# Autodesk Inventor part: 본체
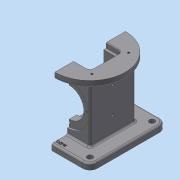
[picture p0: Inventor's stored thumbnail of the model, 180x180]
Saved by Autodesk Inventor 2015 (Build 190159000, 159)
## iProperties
Created: 2021-05
Part Number: 본체
Material: 일반
Document SubType Name: Modeling
Designer: 101258642
Density: 1 g/cm^3
Appearance: 기본값
Author: 101258642
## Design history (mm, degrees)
sketch "스케치6"
  geometry: L1 (37, -37)-(-37, -37); L2 (-37, -37)-(-37, 37); L3 (-37, 37)-(37, 37); L4 (37, 37)-(37, -37); L5 (37, -37)-(-37, 37); L6 (-37, -37)-(37, 37); 1 further point
  constraints: 12 end point, 2 midpoint, 2 parallel, 1 horizontal, 1 perpendicular
  dimensions: "d4" = 74 distance of L2.end L3.end; "d5" = 74 distance of L1.end L2.end
extrude "돌출2" new body sketch "스케치6" stored distance "d6" = 108; taper "d7" = 0 deg
sketch "스케치7"
  geometry: C1 r 57.5 at (0, 0); 1 further point
  constraints: 1 centre point, 1 coincident
  dimensions: "d8" = 57.5 radius of C1
extrude "돌출3" join sketch "스케치7" distance "d9" = 10; taper "d10" = 0 deg
sketch "스케치8"
  geometry: L1 (-62.5, 62.5)-(62.5, 62.5); L2 (62.5, 62.5)-(62.5, -62.5); L3 (62.5, -62.5)-(-62.5, -62.5); L4 (-62.5, -62.5)-(-62.5, 62.5); L5 (-62.5, 62.5)-(62.5, -62.5); L6 (62.5, 62.5)-(-62.5, -62.5); 1 further point
  constraints: 12 end point, 2 midpoint, 2 parallel, 1 horizontal, 1 perpendicular
  dimensions: "d11" = 125 distance of L2.end L3.end; "d12" = 125 distance of L1.end L2.end
extrude "돌출4" join sketch "스케치8" distance "d13" = 10; taper "d14" = 0 deg
sketch "스케치9"
  geometry: L1 (-37, 44)-(-57.5, 44) reference; L2 (-57.5, 44)-(-57.5, 54) reference; L3 (-57.5, 54)-(57.5, 54) reference; L4 (57.5, 54)-(57.5, 44) reference; L5 (57.5, 44)-(37, 44) reference; L6 (37, 44)-(37, -44) reference; L7 (37, -44)-(62.5, -44) reference; L8 (62.5, -44)-(62.5, -54) reference; L9 (62.5, -54)-(-62.5, -54) reference; L10 (-62.5, -54)-(-62.5, -44) reference; L11 (-62.5, -44)-(-37, -44) reference; L12 (-37, -44)-(-37, 44) reference; L13 (-37, 0)-(-34, 0); L14 (-34, 0)-(-34, 35); L15 (-34, 35)-(-37, 35); L16 (-37, 35)-(-37, 0); L17 (37, 44)-(37, -44) reference; L18 (37, 35)-(34, 35); L19 (34, 35)-(34, 0); L20 (34, 0)-(37, 0); L21 (37, 0)-(37, 35); L22 (-34, 0)-(34, 0); L23 (34, 0)-(34, 24); L24 (34, 24)-(-34, 24); L25 (-34, 24)-(-34, 0); 1 further point
  constraints: 24 end point, 6 parallel, 3 horizontal, 3 perpendicular, 3 point on line, 1 midpoint
  dimensions: "d15" = 54 distance between parallel lines of L9 L13; "d16" = 3 distance of L14.end L15.end; "d17" = 3 distance of L18.start L18.end; "d18" = 48 diameter of L24 L22; "d19" = 70 diameter of L15 L22; "d20" = 70 diameter of L18 L20
revolve "회전1" sketch "스케치9" stored, may be unused: angle "d21" = 90 deg
sketch "스케치11"
  geometry: L1 (-26, 26)-(26, 26); L2 (26, 26)-(26, -26); L3 (26, -26)-(-26, -26); L4 (-26, -26)-(-26, 26); L5 (-26, 26)-(26, -26); L6 (26, 26)-(-26, -26); C1 r 57.5 at (0, 0) reference
  constraints: 12 end point, 2 midpoint, 2 parallel, 1 horizontal, 1 perpendicular
  dimensions: "d26" = 52 distance of L2.end L3.end; "d27" = 52 distance of L1.end L2.end
extrude "돌출6" cut sketch "스케치11" distance "d28" = 8; taper "d29" = 0 deg
sketch "스케치12" dims "d30" = 29
  geometry: C1 r 35 at (0, 0) reference; 2 further points
  constraints: 1 coincident, 1 vertical alignment, 2 other
hole "구멍1" sketch "스케치12" at (0, 29) diameter "d31" = 3.242; stored, may be unused: countersink angle "d35" = 90 deg, drill point angle "d37" = 118 deg; dims "d32" = 8, "d33" = 4, "d34" = 2, "d36" = 10
sketch "스케치13"
  geometry: L1 (-30, 33)-(30, 33); L2 (30, 33)-(30, -33); L3 (30, -33)-(-30, -33); L4 (-30, -33)-(-30, 33); L5 (-30, 33)-(30, -33); L6 (30, 33)-(-30, -33); C1 r 57.5 at (0, 0) reference; 4 further points
  constraints: 12 end point, 4 coincident, 2 midpoint, 2 parallel, 1 horizontal, 1 perpendicular
  dimensions: "d41" = 60 distance of L2.end L3.end; "d42" = 66 distance of L1.end L2.end
hole "구멍2" sketch "스케치13" at (-30, -33), (-30, 33), (30, 33), (30, -33) diameter "d43" = 3.242; stored, may be unused: countersink angle "d47" = 90 deg, drill point angle "d49" = 118 deg; dims "d44" = 8, "d45" = 4, "d46" = 2, "d48" = 10
fillet "모깎기1" dims "d50" = 12
hole "구멍3" diameter "d53" = 9; stored, may be unused: countersink angle "d57" = 90 deg, drill point angle "d59" = 0 deg; dims "d51" = 10, "d52" = 10, "d54" = 8, "d55" = 4, "d56" = 2, "d58" = 10
sketch "스케치15"
  geometry: L1 (26, 46)-(26, 54) reference; L2 (26, 54)-(57.5, 54) reference; L3 (57.5, 54)-(57.5, 44) reference; L4 (57.5, 44)-(37, 44) reference; L5 (37, 44)-(37, 35) reference; L6 (37, 35)-(34, 35) reference; L7 (34, 35)-(34, 30.621) reference; L8 (34, 30.621)-(24, 30.621) reference; L9 (24, 30.621)-(23.026, 29) reference; L10 (23.026, 29)-(24, 27.379) reference; L11 (24, 27.379)-(34, 27.379) reference; L12 (34, 27.379)-(34, 24) reference; L13 (34, 24)-(-34, 24) reference; L14 (-26, 46)-(26, 46) reference; L15 (-34, -24)-(34, -24) reference; L16 (34, -24)-(34, -27.379) reference; L17 (34, -27.379)-(24, -27.379) reference; L18 (24, -27.379)-(23.026, -29) reference; L19 (23.026, -29)-(24, -30.621) reference; L20 (24, -30.621)-(34, -30.621) reference; L21 (34, -30.621)-(34, -35) reference; L22 (34, -35)-(37, -35) reference; L23 (37, -35)-(37, -44) reference; L24 (37, -44)-(62.5, -44) reference; L25 (62.5, -44)-(62.5, -54) reference; L26 (62.5, -54)-(-62.5, -54) reference; L27 (-62.5, -54)-(-62.5, -44) reference; L28 (-62.5, -44)-(-37, -44) reference; L29 (-37, -44)-(-37, -35) reference; L30 (-37, -35)-(-34, -35) reference; L31 (-34, -35)-(-34, -30.621) reference; L32 (-34, -30.621)-(-24, -30.621) reference; L33 (-24, -30.621)-(-23.026, -29) reference; L34 (-23.026, -29)-(-24, -27.379) reference; L35 (-24, -27.379)-(-34, -27.379) reference; L36 (-34, -27.379)-(-34, -24) reference; L37 (-37, 44)-(-57.5, 44) reference; L38 (-57.5, 44)-(-57.5, 54) reference; L39 (-57.5, 54)-(-26, 54) reference; L40 (-26, 54)-(-26, 46) reference; L41 (-34, 24)-(-34, 27.379) reference; L42 (-34, 27.379)-(-24, 27.379) reference; L43 (-24, 27.379)-(-23.026, 29) reference; L44 (-23.026, 29)-(-24, 30.621) reference; L45 (-24, 30.621)-(-34, 30.621) reference; L46 (-34, 30.621)-(-34, 35) reference; L47 (-34, 35)-(-37, 35) reference; L48 (-37, 35)-(-37, 44) reference; L49 (-28, -54)-(-24.826, -36); L50 (-24.826, -36)-(0, -36); L51 (0, -36)-(0, -54); L52 (50.5, -54)-(-50.5, -54) reference; L53 (-28, -54)-(0, -54); 2 further points
  constraints: 8 end point, 2 midpoint, 1 collinear, 1 horizontal, 1 point on line, 1 vertical alignment
  dimensions: "d66" = 80 deg angle of L53 L49; "d67" = 56 diameter of L49.start L51; "d68" = 18 distance between parallel lines of L53 L50
revolve "회전2" sketch "스케치15" stored, may be unused: angle "d69" = 90 deg
sketch "스케치21"
  geometry: L1 (-22, 22)-(22, 22); L2 (22, 22)-(22, -22); L3 (22, -22)-(-22, -22); L4 (-22, -22)-(-22, 22); L5 (-22, 22)-(22, -22); L6 (22, 22)-(-22, -22); 1 further point
  constraints: 12 end point, 2 midpoint, 2 parallel, 1 horizontal, 1 perpendicular
  dimensions: "d71" = 44 distance of L2.end L3.end; "d72" = 44 distance of L1.end L2.end
extrude "돌출7" cut sketch "스케치21" distance "d73" = 74; taper "d74" = 0 deg
sketch "스케치23"
  geometry: L1 (-13.5, -98)-(87.5, -98) reference; 3 further points
  constraints: 2 vertical alignment
  dimensions: "d75" = 43 distance of point (37, -61) point (37, -18); "d76" = 37 distance from line of L1 point (37, -61)
hole "구멍4" sketch "스케치23" at (37, -18), (37, -61) diameter "d77" = 4.134; stored, may be unused: countersink angle "d81" = 90 deg, drill point angle "d83" = 118 deg; dims "d78" = 10, "d79" = 4, "d80" = 2, "d82" = 30
fillet "모깎기2" dims "d84" = 3
fillet "모깎기3" dims "d85" = 3
fillet "모깎기4" dims "d86" = 3
fillet "모깎기5" dims "d87" = 3
fillet "모깎기7" dims "d92" = 6
chamfer "모따기2" distance "d93" = 1; stored, may be unused: second distance "d94" = 2, angle "d95" = 45 deg
node "작업 평면1"
sketch "스케치24"
  geometry: L1 (51.783, -16.923)-(51.783, 16.26); L2 (51.783, 16.26)-(58.217, 16.26); L3 (58.217, 16.26)-(58.217, -16.923); L4 (58.217, -16.923)-(51.783, -16.923); 2 further points
  constraints: 1 midpoint, 2 other
  dimensions: "d98" = 55 horizontal distance of point (0, 0) point (55, 16.26)
feature "엠보싱1" sketch "스케치24" dims "d4" = 74, "d5" = 74, "d99" = 0.5, "d100" = 0
fillet "모깎기8" dims "d101" = 3
node "솔리드2"
pattern_circular "원형 패턴1" dims angle "d39" = 360 deg
mirror "대칭1"
pattern_linear "직사각형 패턴1"
node "절단 모서리 투영1"
node "절단 모서리 투영2"
